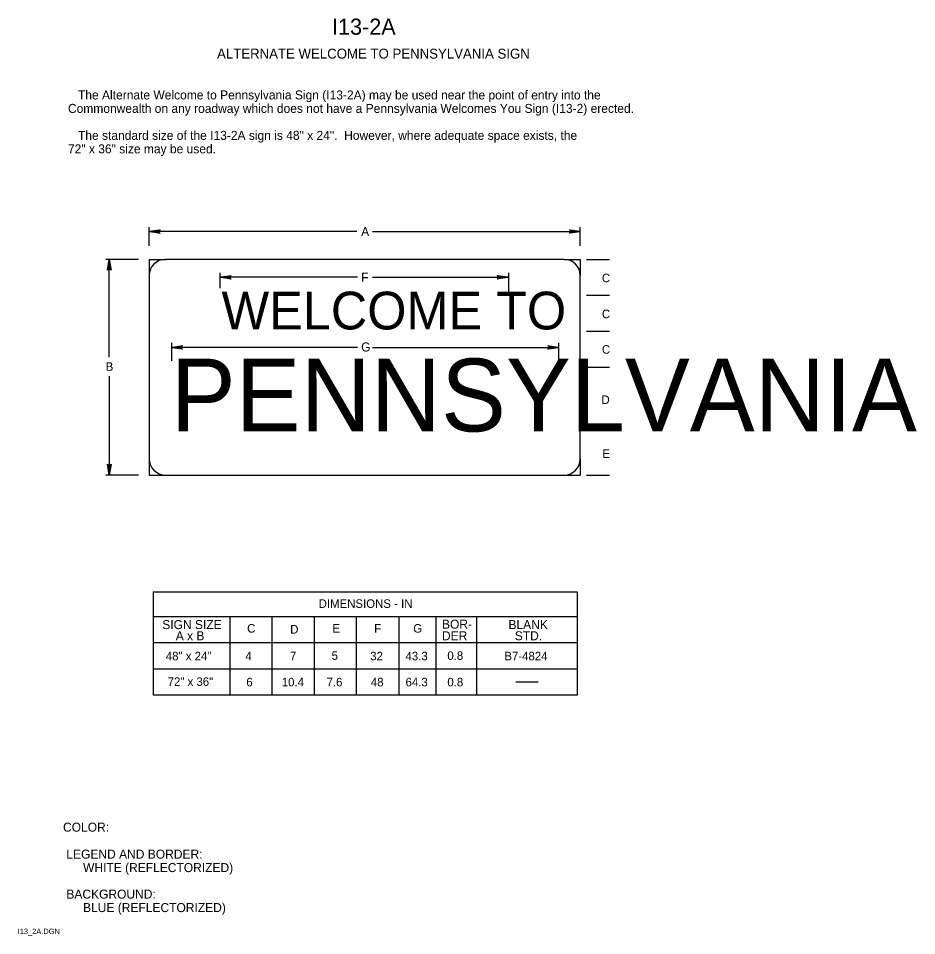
# Model space of a CAD drawing. Extents: x 0.013 to 0.263, y 0.004 to 0.259.
import ezdxf

# ---------------------------------------------------------------- set-up
doc = ezdxf.new("R2010")
doc.units = 0
for name, color, linetype in [('1', 7, 'Continuous'), ('2', 7, 'Continuous'), ('3', 7, 'Continuous')]:
    doc.layers.add(name, color=color, linetype=linetype)

# ---------------------------------------------------------------- blocks, each defined once
blk = doc.blocks.new('RARROW')
at = {"layer": '3'}
for p, q in [((-2.156, 0.285), (-2.2665, 0.384625)), ((-2.2665, 0.384625), (0, 0)), ((0, 0), (-2.2665, -0.379125)), ((-2.156, 0.285), (-2.075625, 0.12075)), ((0, 0), (-2.156, 0.285)), ((-2.14975, -0.2705), (0, 0)), ((-2.075625, 0.12075), (0, 0)), ((0, 0), (-2.074, -0.108)), ((-2.2665, -0.379125), (-2.14975, -0.2705)), ((-2.074, -0.108), (-2.14975, -0.2705))]:
    blk.add_line(p, q, dxfattribs=at)

msp = doc.modelspace()

# ---------------------------------------------------------------- linework, layer by layer
at = {"layer": '3'}
for p, q in [((0.04913, 0.19587), (0.04913, 0.20112)), ((0.10687, 0.19987), (0.04913, 0.19987)), ((0.11125, 0.19987), (0.16912, 0.19987)), ((0.16912, 0.19587), (0.16912, 0.20112)), ((0.04612, 0.19212), (0.037, 0.19212)), ((0.038, 0.16487), (0.038, 0.19212)), ((0.04913, 0.19212), (0.04913, 0.18763)), ((0.04913, 0.19212), (0.05362, 0.19212)), ((0.16462, 0.19212), (0.05362, 0.19212)), ((0.16462, 0.19212), (0.16912, 0.19212)), ((0.16912, 0.19212), (0.16912, 0.18763)), ((0.17087, 0.19212), (0.17725, 0.19212)), ((0.04913, 0.18763), (0.04913, 0.13662)), ((0.06887, 0.18413), (0.06887, 0.18838)), ((0.1071, 0.18713), (0.0691, 0.18713)), ((0.11123, 0.18713), (0.14923, 0.18713)), ((0.14923, 0.18275), (0.14923, 0.18838)), ((0.16912, 0.13662), (0.16912, 0.18763)), ((0.17087, 0.18213), (0.17725, 0.18213)), ((0.17087, 0.17213), (0.17725, 0.17213)), ((0.05538, 0.16387), (0.05538, 0.16887)), ((0.16312, 0.16287), (0.16312, 0.16887)), ((0.10712, 0.16762), (0.05538, 0.16762)), ((0.11129, 0.16762), (0.16312, 0.16762)), ((0.17087, 0.16212), (0.17725, 0.16212)), ((0.038, 0.15963), (0.038, 0.13212)), ((0.17087, 0.14463), (0.17725, 0.14463)), ((0.04913, 0.13662), (0.04913, 0.13212)), ((0.16912, 0.13662), (0.16912, 0.13212)), ((0.04612, 0.13212), (0.037, 0.13212)), ((0.04913, 0.13212), (0.05362, 0.13212)), ((0.05362, 0.13212), (0.16462, 0.13212)), ((0.16462, 0.13212), (0.16912, 0.13212)), ((0.17087, 0.13212), (0.17725, 0.13212)), ((0.05025, 0.09963), (0.16825, 0.09963)), ((0.05025, 0.09963), (0.05025, 0.07088)), ((0.16825, 0.09963), (0.16825, 0.07088)), ((0.16825, 0.09963), (0.16825, 0.07812)), ((0.16825, 0.09262), (0.05025, 0.09262)), ((0.07157, 0.09279), (0.07157, 0.07088)), ((0.08325, 0.09262), (0.08325, 0.07088)), ((0.095, 0.09262), (0.095, 0.07088)), ((0.10675, 0.09262), (0.10675, 0.07088)), ((0.11857, 0.09267), (0.11857, 0.07088)), ((0.12888, 0.09267), (0.12888, 0.07088)), ((0.14027, 0.09262), (0.14027, 0.07093)), ((0.16825, 0.08538), (0.05025, 0.08538)), ((0.16825, 0.07812), (0.05025, 0.07812)), ((0.15738, 0.0745), (0.15113, 0.0745)), ((0.16825, 0.07088), (0.05025, 0.07088))]:
    msp.add_line(p, q, dxfattribs=at)
for centre, start, end in [((0.05362, 0.18763), 90, 180), ((0.16462, 0.18763), 0, 90), ((0.05362, 0.13662), 180, 270), ((0.16462, 0.13662), 270, 0)]:
    msp.add_arc(centre, 0.0045, start, end, dxfattribs=at)

# ---------------------------------------------------------------- block references
at = {"layer": '3', "xscale": 0.0013236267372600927, "yscale": 0.001309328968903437}
for p, rotation in [((0.04913, 0.19987), 180), ((0.038, 0.19212), 90), ((0.06888, 0.18713), 180), ((0.05538, 0.16762), 180), ((0.038, 0.13212), -90)]:
    msp.add_blockref('RARROW', p, dxfattribs=dict(at, rotation=rotation))
for p in [(0.16912, 0.19987), (0.149, 0.18713), (0.16312, 0.16762)]:
    msp.add_blockref('RARROW', p, dxfattribs=at)

# ---------------------------------------------------------------- texts
at = {"layer": '1'}
for s, height, p in [('I13-2A', 0.0045, (0.1, 0.25462)), ('ALTERNATE WELCOME TO PENNSYLVANIA SIGN', 0.0027503, (0.068, 0.248)), ('COLOR:', 0.0025, (0.02513, 0.03288)), (' LEGEND AND BORDER:', 0.0024998, (0.02513, 0.02538)), ('      WHITE (REFLECTORIZED)', 0.0024998, (0.02513, 0.02163)), (' BACKGROUND:', 0.0024998, (0.02513, 0.01425)), ('      BLUE (REFLECTORIZED)', 0.0024998, (0.02513, 0.0105)), ('I13_2A.DGN', 0.0015, (0.0125, 0.00438))]:
    msp.add_text(s, height=height, dxfattribs=at).set_placement(p)
at = {"layer": '2'}
for s, p in [('   The Alternate Welcome to Pennsylvania Sign (I13-2A) may be used near the point of entry into the', (0.0265, 0.23663)), ('Commonwealth on any roadway which does not have a Pennsylvania Welcomes You Sign (I13-2) erected.', (0.0265, 0.23288)), ('   The standard size of the I13-2A sign is 48" x 24".  However, where adequate space exists, the ', (0.0265, 0.22538)), ('72" x 36" size may be used.', (0.0265, 0.22163))]:
    msp.add_text(s, height=0.0024998, dxfattribs=at).set_placement(p)
at = {"layer": '3'}
for s, height, p in [('A', 0.0025, (0.10812, 0.19862)), ('F', 0.0025, (0.10812, 0.18588)), ('C', 0.00238, (0.17513, 0.18575)), ('WELCOME TO ', 0.0105, (0.06925, 0.17263)), ('C', 0.00238, (0.17513, 0.17575)), ('G', 0.0025, (0.10812, 0.1665)), ('C', 0.00238, (0.17513, 0.16587)), ('B', 0.00238, (0.037, 0.16112)), ('PENNSYLVANIA', 0.02025, (0.05513, 0.14425)), ('D', 0.00238, (0.175, 0.15188)), ('E', 0.00238, (0.17525, 0.13687)), ('DIMENSIONS - IN', 0.0023752, (0.09629, 0.09515)), ('BOR-', 0.0025, (0.13062, 0.08937)), ('SIGN SIZE', 0.0025, (0.05275, 0.08925)), ('C', 0.00238, (0.07637, 0.08825)), ('D', 0.00238, (0.08837, 0.088)), ('E', 0.00238, (0.10013, 0.08825)), ('F', 0.00238, (0.11175, 0.08825)), ('G', 0.00238, (0.12262, 0.08825)), ('BLANK', 0.0025, (0.14913, 0.08925)), ('A x B', 0.0025, (0.0565, 0.08613)), ('DER', 0.0025, (0.13062, 0.08613)), ('STD.', 0.0025, (0.15088, 0.08613)), ('48" x 24"', 0.002375, (0.05375, 0.08056)), ('4', 0.00238, (0.07589, 0.08056)), ('7', 0.00238, (0.08831, 0.08056)), ('5', 0.00238, (0.0999, 0.08069)), ('32', 0.002375, (0.11064, 0.08056)), ('43.3', 0.002375, (0.12047, 0.08056)), ('0.8', 0.002375, (0.13211, 0.08069)), ('B7-4824', 0.002375, (0.14799, 0.08056)), ('72" x 36"', 0.002375, (0.05425, 0.07344)), ('6', 0.00238, (0.07615, 0.07331)), ('10.4', 0.002375, (0.08601, 0.07331)), ('7.6', 0.002375, (0.09849, 0.07331)), ('48', 0.002375, (0.11082, 0.07331)), ('64.3', 0.002375, (0.12047, 0.07331)), ('0.8', 0.002375, (0.13211, 0.07331))]:
    msp.add_text(s, height=height, dxfattribs=at).set_placement(p)

doc.saveas('drawing.dxf')
